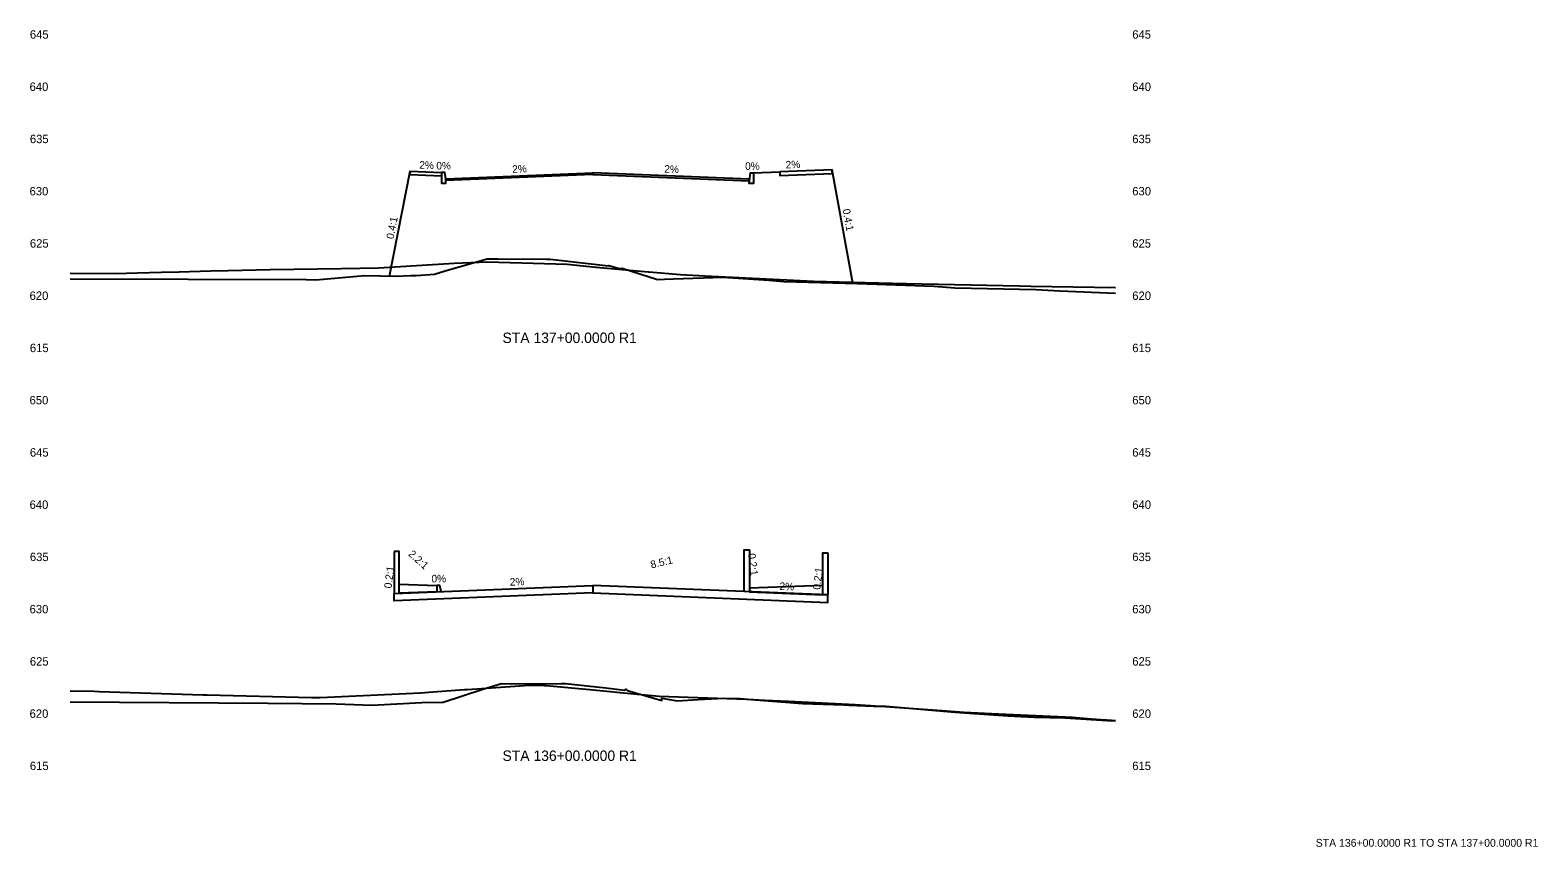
# Model space of a CAD drawing. Extents: x 12 to 301, y 16 to 1707.
# Drawn here: x 12.4 to 300.8, y 15.9 to 172.2 of the extents above; entities that cross this region are included whole.
import ezdxf

# ---------------------------------------------------------------- set-up
doc = ezdxf.new("R2010")
doc.units = 0
for name, color, linetype in [('BORD_text_large_2', 7, 'Continuous'), ('Bridge_Railing', 7, 'Continuous'), ('Default', 7, 'Continuous'), ('Draft_Corr_Range_Functional', 7, 'Continuous'), ('Draft_XS_Point_Label_Indicator', 7, 'Continuous'), ('Draft_XS_Text', 7, 'Continuous'), ('Grade_Veg_Grass', 7, 'Continuous'), ('P_XS_Sections', 7, 'Continuous'), ('Road_Curb', 7, 'Continuous'), ('Road_Pave_Asphalt', 7, 'Continuous'), ('Road_Pave_Concrete', 7, 'Continuous'), ('Road_Sidewalk', 7, 'Continuous'), ('Terrain_Exterior', 7, 'Continuous')]:
    doc.layers.add(name, color=color, linetype=linetype)

msp = doc.modelspace()

# ---------------------------------------------------------------- linework, layer by layer
at = {"layer": 'Bridge_Railing'}
for points in [[(82, 72.44), (82, 64.4), (83, 64.44), (83, 72.44), (82, 72.44)], [(150, 72.76), (150, 64.72), (149, 64.76), (149, 72.76), (150, 72.76)], [(165, 72.16), (165, 64.12), (164, 64.16), (164, 72.16), (165, 72.16)]]:
    msp.add_lwpolyline(points, dxfattribs=at)
at = {"layer": 'Default'}
for points in [[(20, 124.65), (65.18, 124.48), (67.05, 124.41), (76.38, 125.25), (82.4, 125.12), (85.11, 125.26), (86.22, 125.29), (89.74, 125.49), (91.76, 126.15), (99.53, 128.39), (99.65, 128.43), (101.91, 128.44), (111.15, 128.42), (111.3, 128.42), (111.86, 128.37), (114.15, 128.13), (123.01, 127.09), (123.1, 127.15), (125.12, 126.58), (125.66, 126.7), (132.38, 124.47), (133.74, 124.55), (135.43, 124.63), (144.89, 124.97), (153.69, 124.35), (156.54, 124.12), (168.32, 123.81), (170.65, 123.75), (185.33, 123.22), (189.27, 122.93), (204.79, 122.6), (209.34, 122.3), (220, 121.9)], [(20, 43.65), (57.87, 43.42), (70.93, 43.28), (77.75, 43.01), (87.33, 43.52), (91.41, 43.61), (98.96, 46.06), (102.56, 47.19), (106, 47.12), (114.02, 47.16), (114.31, 47.16), (114.52, 47.16), (114.77, 47.16), (122.5, 46.33), (126.1, 45.89), (126.4, 46.07), (126.68, 45.8), (133.23, 43.94), (133.25, 44.38), (136.15, 43.88), (140.16, 44.12), (145.14, 44.36), (148.25, 44.33), (150.29, 44.12), (160.15, 43.32), (168.02, 43.09), (169.04, 43.03), (173.72, 42.83), (176.1, 42.85), (189.32, 41.71), (199.4, 41.01), (204.51, 40.7), (210.34, 40.61), (218.4, 40.08), (220, 40.04)]]:
    msp.add_lwpolyline(points, dxfattribs=at)
at = {"layer": 'Grade_Veg_Grass'}
for points in [[(81.1, 125.15), (81.1, 125.15), (85.1, 145.21)], [(150.78, 144.89), (155.78, 145.09)], [(169.78, 123.77), (165.78, 145.49), (165.78, 145.49)]]:
    msp.add_lwpolyline(points, dxfattribs=at)
at = {"layer": 'Road_Curb'}
for points in [[(91.1, 144.97), (91.1, 142.97), (91.93, 142.97), (91.93, 143.8), (91.7, 144.97), (91.1, 144.97)], [(150.78, 144.89), (150.78, 142.89), (149.95, 142.89), (150.18, 144.89), (150.78, 144.89)], [(90.17, 65.93), (90.17, 64.73), (91, 64.76), (90.77, 65.93), (90.17, 65.93)]]:
    msp.add_lwpolyline(points, dxfattribs=at)
at = {"layer": 'Road_Pave_Asphalt'}
for points in [[(91.93, 143.8), (120, 144.92), (120, 144.59), (120, 144.59), (91.93, 143.47), (91.93, 143.47), (91.93, 143.47), (91.93, 143.8), (91.93, 143.8)], [(120, 144.92), (120, 144.92), (120, 144.59), (120, 144.59), (120, 144.59), (149.95, 143.39), (149.95, 143.39), (149.95, 143.72), (120, 144.92)]]:
    msp.add_lwpolyline(points, dxfattribs=at)
at = {"layer": 'Road_Pave_Concrete'}
for points in [[(120, 65.92), (120, 64.5), (82, 62.98), (82, 64.4), (120, 65.92)], [(120, 65.92), (120, 64.5), (165, 62.7), (165, 64.12), (120, 65.92)]]:
    msp.add_lwpolyline(points, dxfattribs=at)
at = {"layer": 'Road_Sidewalk'}
for points in [[(91.1, 144.97), (91.1, 144.3), (85.1, 144.54), (85.1, 145.21), (91.1, 144.97)], [(155.78, 145.09), (155.78, 144.42), (165.78, 144.82), (165.78, 145.49), (155.78, 145.09)], [(90.17, 65.93), (90.17, 64.73), (83, 64.44), (83, 66.21), (90.17, 65.93)], [(150, 65.39), (150, 64.72), (164, 64.16), (164, 65.95), (150, 65.39)]]:
    msp.add_lwpolyline(points, dxfattribs=at)
at = {"layer": 'Terrain_Exterior'}
for points in [[(20, 125.74), (28.61, 125.62), (32.9, 125.76), (37.48, 125.92), (40.88, 126), (46.9, 126.15), (50.24, 126.23), (58.28, 126.4), (71.87, 126.6), (79.07, 126.71), (93.5, 127.62), (99.87, 127.9), (110.76, 127.55), (115.14, 127.41), (120.57, 126.85), (120.66, 126.84), (130.63, 126), (130.74, 125.99), (136.77, 125.48), (141.46, 125.23), (158.4, 124.35), (162.25, 124.2), (169.59, 124), (179.91, 123.72), (180.03, 123.72), (183.05, 123.64), (201.66, 123.27), (203.84, 123.25), (220, 122.95)], [(20, 45.74), (24.59, 45.68), (24.63, 45.68), (25.6, 45.65), (45.43, 45.02), (46.22, 44.99), (66.22, 44.46), (67.85, 44.48), (87.02, 45.41), (89.48, 45.6), (95.44, 46), (95.96, 46.04), (107.81, 46.83), (110.76, 46.79), (111.11, 46.78), (119.43, 46), (128.48, 45.15), (128.61, 45.14), (132.74, 44.76), (149.4, 44.16), (149.57, 44.15), (152.91, 44), (154.37, 43.93), (157.43, 43.78), (170.2, 43.15), (175.03, 42.84), (176.01, 42.78), (186.77, 42), (187.67, 41.94), (190.99, 41.7), (197.64, 41.39), (211.79, 40.72), (215.34, 40.43), (219.27, 40.12), (220, 40.06)]]:
    msp.add_lwpolyline(points, dxfattribs=at)

# ---------------------------------------------------------------- texts
at = {"layer": 'BORD_text_large_2'}
msp.add_text('STA 136+00.0000 R1 TO STA 137+00.0000 R1', height=1.5, dxfattribs=at).set_placement((258.32, 15.92))
at = {"layer": 'Draft_Corr_Range_Functional'}
for p in [(81.99, 72.43), (82.99, 72.43), (148.99, 72.75), (149.99, 72.75), (163.99, 72.15), (164.99, 72.15), (81.99, 64.39), (81.99, 64.39), (82.99, 66.2), (82.99, 64.43), (90.16, 65.92), (90.76, 65.92), (90.99, 64.75), (119.99, 65.91), (148.99, 64.75), (149.99, 65.38), (149.99, 64.71), (163.99, 65.94), (163.99, 64.15), (164.99, 64.11), (164.99, 64.11)]:
    msp.add_text('X', height=0.024, dxfattribs=at).set_placement(p)
at = {"layer": 'Draft_XS_Point_Label_Indicator'}
for p in [(85.08, 145.19), (91.08, 144.95), (91.69, 144.95), (119.99, 144.91), (119.99, 144.91), (150.17, 144.88), (150.77, 144.88), (155.77, 145.08), (165.77, 145.48), (91.92, 143.79), (149.94, 143.71), (81.08, 125.13), (169.77, 123.76), (119.99, 65.91)]:
    msp.add_text('X', height=0.024, dxfattribs=at).set_placement(p)
at = {"layer": 'Draft_XS_Text'}
for s, height, p in [('645', 1.608, (12.32, 170.6)), ('645', 1.608, (223.22, 170.6)), ('640', 1.608, (12.26, 160.6)), ('640', 1.608, (223.22, 160.6)), ('635', 1.608, (12.32, 150.6)), ('635', 1.608, (223.22, 150.6)), ('0%', 1.44, (90.08, 145.57)), ('0%', 1.44, (90.08, 145.57)), ('0%', 1.44, (90.08, 145.57)), ('0%', 1.44, (149.16, 145.49)), ('0%', 1.44, (149.16, 145.49)), ('0%', 1.44, (149.16, 145.49)), ('630', 1.608, (12.26, 140.6)), ('630', 1.608, (223.22, 140.6)), ('625', 1.608, (12.32, 130.6)), ('625', 1.608, (223.22, 130.6)), ('620', 1.608, (12.26, 120.6)), ('620', 1.608, (223.22, 120.6)), ('STA 137+00.0000 R1', 1.992, (102.74, 112.35)), ('615', 1.608, (12.32, 110.6)), ('615', 1.608, (223.22, 110.6)), ('650', 1.608, (12.26, 100.6)), ('650', 1.608, (223.22, 100.6)), ('645', 1.608, (12.32, 90.6)), ('645', 1.608, (223.22, 90.6)), ('640', 1.608, (12.26, 80.6)), ('640', 1.608, (223.22, 80.6)), ('635', 1.608, (12.32, 70.6)), ('635', 1.608, (223.22, 70.6)), ('630', 1.608, (12.26, 60.6)), ('630', 1.608, (223.22, 60.6)), ('625', 1.608, (12.32, 50.6)), ('625', 1.608, (223.22, 50.6)), ('620', 1.608, (12.26, 40.6)), ('620', 1.608, (223.22, 40.6)), ('615', 1.608, (12.32, 30.6)), ('STA 136+00.0000 R1', 1.992, (102.74, 32.35)), ('615', 1.608, (223.22, 30.6))]:
    msp.add_text(s, height=height, dxfattribs=at).set_placement(p)
for s, rotation, p in [('2%', 357.7094, (86.81, 145.74)), ('2%', 357.7094, (86.81, 145.74)), ('2%', 357.7094, (86.81, 145.74)), ('2%', 2.2906, (156.94, 145.74)), ('2%', 2.2906, (156.94, 145.74)), ('2%', 2.2906, (156.94, 145.74)), ('2%', 2.2906, (104.63, 144.91)), ('2%', 2.2906, (104.63, 144.91)), ('2%', 2.2906, (104.63, 144.91)), ('2%', 357.7094, (133.68, 144.97)), ('2%', 357.7094, (133.68, 144.97)), ('2%', 357.7094, (133.68, 144.97)), ('0.4:1', 78.7224, (81.88, 132.16)), ('0.4:1', 78.7224, (81.88, 132.16)), ('0.4:1', 78.7224, (81.88, 132.16)), ('0.4:1', 280.4363, (167.79, 137.89)), ('0.4:1', 280.4363, (167.79, 137.89)), ('0.4:1', 280.4363, (167.79, 137.89)), ('2.2:1', 317.7343, (84.62, 71.78)), ('2.2:1', 317.7343, (84.62, 71.78)), ('2.2:1', 317.7343, (84.62, 71.78)), ('0.2:1', 82.9101, (81.51, 65.32)), ('0.2:1', 82.9101, (81.51, 65.32)), ('0.2:1', 82.9101, (81.51, 65.32)), ('8.5:1', 13.2714, (131.25, 69.19)), ('8.5:1', 13.2714, (131.25, 69.19)), ('8.5:1', 13.2714, (131.25, 69.19)), ('0.2:1', 277.0899, (149.7, 71.99)), ('0.2:1', 277.0899, (149.7, 71.99)), ('0.2:1', 277.0899, (149.7, 71.99)), ('0.2:1', 82.875, (163.51, 65.06)), ('0.2:1', 82.875, (163.51, 65.06)), ('0.2:1', 82.875, (163.51, 65.06)), ('0%', 0, (89.15, 66.53)), ('0%', 0, (89.15, 66.53)), ('0%', 0, (89.15, 66.53)), ('2%', 2.2906, (104.16, 65.89)), ('2%', 2.2906, (104.16, 65.89)), ('2%', 2.2906, (104.16, 65.89)), ('2%', 357.7094, (155.71, 65.09)), ('2%', 357.7094, (155.71, 65.09)), ('2%', 357.7094, (155.71, 65.09))]:
    msp.add_text(s, height=1.44, rotation=rotation, dxfattribs=at).set_placement(p)
at = {"layer": 'P_XS_Sections'}
for p in [(20, 110), (20, 30)]:
    msp.add_text('-', height=0.0001, dxfattribs=at).set_placement(p)

doc.saveas('drawing.dxf')
